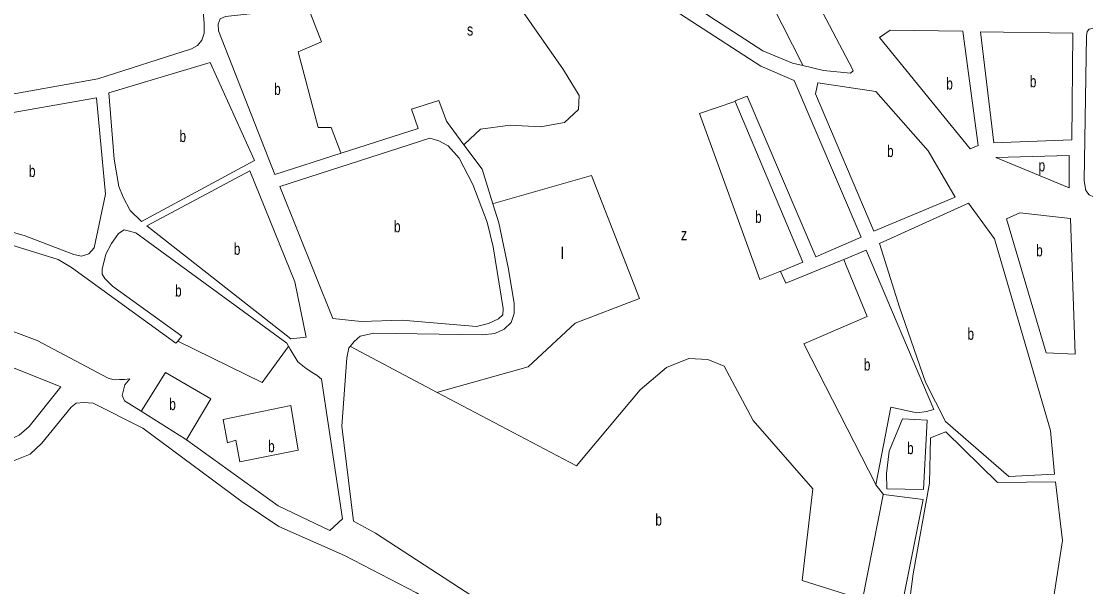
# Model space of a CAD drawing. Extents: x 639657 to 671642, y 222838 to 252123.
# Drawn here: x 648393 to 649296, y 242810 to 243290 of the extents above; entities that cross this region are included whole.
import ezdxf

# ---------------------------------------------------------------- set-up
doc = ezdxf.new("R2010")
doc.units = 0
doc.header["$LTSCALE"] = 4
doc.layers.add('1', color=7, linetype='Continuous', lineweight=13)
doc.layers.add('21', color=7, linetype='Continuous', lineweight=13)
doc.layers.add('7', color=7, linetype='Continuous')

msp = doc.modelspace()

# ---------------------------------------------------------------- linework, layer by layer
at = {"layer": '1'}
for p, q in [((648618.55, 243016.9), (648619.936, 243014.269)), ((648476.85, 242986.046), (648476.48, 242986.027)), ((648532.46, 242935.52), (648494.743, 242959.06)), ((648532.46, 242935.52), (648533.215, 242934.977))]:
    msp.add_line(p, q, dxfattribs=at)
for points in [[(649098.36, 243249.17), (648939.37, 243550.8), (648819.54, 243488)], [(648793.12, 243492.45), (648801.618, 243464.623), (648893.09, 243350.7), (648977.18, 243293.76), (649022.12, 243264.66), (649047.26, 243254.2), (649056.254, 243252.103)], [(648903.422, 243327.55), (649020.43, 243251.77), (649048.8, 243239.6), (649105.61, 243106.79), (649067.23, 243089.94), (649008.91, 243226.18), (648998.62, 243222.29), (648998.829, 243221.793)], [(648664.469, 243177.792), (648608.3, 243159.7), (648560.33, 243281.59), (648560.31, 243287.17), (648561.8, 243291.9), (648566.31, 243293.63), (648631.33, 243300.87), (648636.234, 243301.822)], [(649056.254, 243252.103), (649073.68, 243248.04), (649096.44, 243245.73), (649098.8, 243247.67), (649098.36, 243249.17)], [(648768.656, 243185.066), (648753.94, 243204.94), (648747.46, 243222.54), (648724.29, 243215.18), (648729.91, 243198.87), (648664.469, 243177.792)], [(648998.829, 243221.793), (649056.08, 243085.62), (649037.21, 243077.63)], [(648793.192, 243134.944), (648784.1, 243164.21), (648768.656, 243185.066)], [(648672.049, 243014.121), (648675.43, 243018.33), (648680.57, 243022.64), (648692.16, 243025.24), (648784.47, 243023.75), (648794.77, 243025.06), (648802.7, 243028.73), (648808.7, 243034.33), (648811.26, 243041.85), (648811.23, 243050.66), (648806.22, 243080.93), (648798.17, 243118.92), (648793.192, 243134.944)], [(648476.48, 242986.027), (648471.926, 242985.795), (648466.808, 242987.174), (648406.66, 243018.97), (648336.83, 243045), (648344.63, 243097), (648343.674, 243102.64), (648346.179, 243107.509), (648348.428, 243109.13), (648351.99, 243110.07), (648424.51, 243087.74), (648435.69, 243080.89), (648524.382, 243016.683)], [(648618.55, 243016.9), (648490.36, 243110.23), (648480.48, 243113), (648475.55, 243109.77), (648469.77, 243101.38), (648464.86, 243092.13), (648461.67, 243079.45), (648461.69, 243075.37), (648464.06, 243071.73), (648470.51, 243065.08)], [(649090.888, 243087.789), (649109.93, 243095.63), (649167.18, 242960.69), (649161.17, 242958.75), (649152.8, 242957.87), (649130.89, 242962.61), (649118.19, 242896.58), (649124.44, 242888.65)], [(649037.21, 243077.63), (649041.74, 243067.55), (649090.888, 243087.789)], [(648470.51, 243065.08), (648529.38, 243022.698), (648525.894, 243018.503), (648524.382, 243016.683)], [(648619.936, 243014.269), (648621.321, 243011.64), (648627.841, 243000.923), (648634.827, 242995.332), (648641.37, 242990.97)], [(648665.1, 242946.58), (648669.23, 243004.34), (648670.94, 243012.74), (648672.049, 243014.121)], [(648665.74, 242867.98), (648647.83, 242986.27), (648644.17, 242989.48), (648641.37, 242990.97)], [(648494.743, 242959.06), (648480.672, 242967.842), (648478.809, 242972.501), (648481.138, 242981.354), (648485.329, 242986.479), (648480.672, 242986.013), (648476.85, 242986.046)], [(648382.38, 242915.24), (648400.83, 242922.59), (648410.68, 242932.06), (648435.5, 242962.62), (648439.79, 242965.85), (648446.22, 242966.51), (648454.17, 242965.88), (648496.31, 242944.72), (648580.41, 242882.22), (648611.6, 242861.47), (648667.27, 242836.69), (648728.54, 242805.27), (648806.18, 242754.36), (648776.24, 242711.12), (648765.11, 242696.28), (648758.26, 242690.25), (648745.61, 242683.78), (648738.74, 242682.69), (648711.9, 242685.84), (648588.37, 242714.31), (648475.98, 242756.77), (648376.31, 242775.21)], [(649022.21, 242746.46), (648995.12, 242682.84), (648908.11, 242705.81), (648793.03, 242790.99), (648693.68, 242855.59), (648674.98, 242865.86), (648665.1, 242946.58)], [(648533.215, 242934.977), (648610.97, 242879.02), (648655.03, 242857.86), (648665.74, 242867.98)], [(649110.161, 242656.114), (649119.885, 242655.479), (649134.564, 242705.482), (649144.699, 242702.684), (649130.67, 242653.91), (649180.69, 242649.81), (649206.18, 242670.48), (649246.99, 242659.85), (649276.53, 242849.52), (649270.39, 242899.32), (649221.23, 242898.55), (649177.53, 242941.61), (649164.45, 242936.64), (649163.7, 242897.98), (649149.592, 242821.221), (649145.95, 242793.15), (649137.69, 242749.539)], [(649124.44, 242888.65), (649158.15, 242884.22), (649136.34, 242775.52), (649122.51, 242729.53), (649115.47, 242710.62), (649031.261, 242742.982)]]:
    msp.add_lwpolyline(points, dxfattribs=at)
for points in [[(648541.65, 243363.17), (648413.08, 243359.64), (648361.44, 243236.22), (648361.03, 243231.06), (648363.83, 243226.34), (648369.42, 243225.07), (648458.03, 243240.96), (648537.61, 243266.28), (648542.76, 243269.09), (648546.39, 243273.61), (648548.31, 243279.63), (648548.29, 243288)], [(649204.79, 243184.35), (649191.87, 243281.19), (649130.26, 243282.11), (649121.05, 243276.07), (649198.15, 243181.54)], [(649284.42, 243189.27), (649285.26, 243279.7), (649206.9, 243280.79), (649218.1, 243186.75)], [(649416.76, 243150.08), (649420.5, 243278.96), (649419.63, 243281.32), (649415.12, 243283.67), (649303.28, 243284.25), (649298.99, 243282.95), (649297.27, 243281.02), (649296.64, 243277.36), (649294.82, 243154.51), (649296.13, 243146.13), (649298.93, 243142.71), (649302.58, 243141), (649332, 243137.42), (649352.4, 243133.6), (649377.75, 243126.79), (649393.21, 243124.9), (649402.44, 243125.78), (649409.3, 243128.16), (649413.59, 243131.61), (649417.22, 243137.63), (649418.07, 243142.14)], [(648591.09, 243171.69), (648553.31, 243254.72), (648467.3, 243228.95), (648471.95, 243172.91), (648475.87, 243149.72), (648479.55, 243140.71), (648485.59, 243129.34), (648495.27, 243119.91)], [(649117.95, 243230.1), (649068.77, 243237.5), (649066.86, 243228.26), (649116.33, 243111.76), (649185.38, 243140.71), (649162.52, 243179.74)], [(648464.73, 243143.03), (648456.986, 243224.773), (648369.833, 243209.6), (648360.096, 243209.938), (648353.72, 243208.468), (648345.072, 243203.874), (648340.285, 243199.413), (648335.092, 243191.11), (648333.177, 243184.853), (648332.605, 243178.335), (648340.03, 243132.64), (648341.237, 243127.725), (648342.994, 243124.787), (648345.572, 243122.536), (648349.293, 243121.063), (648395.7, 243108.07), (648437.853, 243092.054), (648444.279, 243090.654), (648450.583, 243092.658), (648455.04, 243097.547)], [(648739.6, 243190.73), (648612.62, 243149.62), (648657.35, 243037.83), (648681.4, 243035.1), (648716.39, 243036.26), (648779.3, 243030.82), (648789.6, 243033.43), (648797.96, 243037.31), (648801.6, 243040.97), (648802.01, 243046.13), (648793.5, 243098.51), (648788.3, 243119.33), (648776.19, 243151.3), (648764.54, 243173.61), (648755.28, 243184.11), (648747.33, 243188.39)], [(649219.797, 243174.283), (649282.052, 243175.784), (649282.052, 243148.51)], [(648621.76, 243020.56), (648634.85, 243021.88), (648625.28, 243068.68), (648587.04, 243162.87), (648499.58, 243116.27)], [(649218.74, 243105.14), (649196.55, 243135.58), (649121.08, 243101.24), (649138.18, 243047.38), (649160.25, 242983.87), (649177.08, 242950.41), (649230.87, 242903.73), (649269.51, 242905.76), (649266.19, 242942.9)], [(649287.27, 243007.38), (649283.31, 243122.48), (649240.15, 243127.31), (649229, 243122.13), (649262.58, 243008.61)], [(648399.77, 242946.15), (648426.73, 242979.72), (648375.15, 243000.42), (648332.399, 243014.709), (648329.742, 243015.368), (648326.131, 243014.92), (648321.816, 243011.66), (648320.242, 243006.487), (648320.72, 243003.791), (648322.566, 243000.707), (648332.976, 242959.498), (648338.939, 242948.566), (648344.684, 242942.536), (648351.557, 242937.831), (648363.315, 242933.693), (648375.776, 242933.391), (648383.871, 242935.351), (648391.382, 242938.951)], [(649158.56, 242892.81), (649161.62, 242951.45), (649140.8, 242952.68), (649129.28, 242925.38), (649126.97, 242906.27), (649127.43, 242893.38)]]:
    msp.add_lwpolyline(points, close=True, dxfattribs=at)
at = {"layer": '21'}
for points in [[(648819.54, 243488), (648838.539, 243454.818), (648923.817, 243500.974), (648956.669, 243441.531), (648927.312, 243425.446), (648948.281, 243389.78), (648977.639, 243407.263), (649056.001, 243252.603), (649056.254, 243252.103)], [(648768.656, 243185.066), (648769.156, 243185.535), (648782.619, 243198.163), (648807.783, 243201.659), (648833.646, 243200.261), (648853.917, 243203.757), (648865.8, 243214.947), (648866.499, 243226.835), (648853.218, 243248.515), (648811.863, 243307.564)], [(648636.234, 243301.822), (648636.428, 243301.322), (648647.712, 243272.292), (648628.14, 243263.9), (648644.916, 243199.561), (648656.1, 243199.561), (648664.277, 243178.292), (648664.469, 243177.792)], [(649037.21, 243077.63), (649036.71, 243077.439), (649019.58, 243070.884), (648968.553, 243211.45), (648998.329, 243221.622), (648998.829, 243221.793)], [(648746, 242975.11), (648746.499, 242975.25), (648823.161, 242996.755), (648863.004, 243033.82), (648917.526, 243054.8), (648876.984, 243159), (648793.692, 243135.088), (648793.192, 243134.944)], [(649090.888, 243087.789), (649092.946, 243082.789), (649110.798, 243039.414), (649056.975, 243016.336), (649117.934, 242897.08), (649118.19, 242896.58)], [(648525.894, 243018.503), (648526.394, 243018.258), (648597.39, 242983.468), (648619.453, 243013.61), (648619.936, 243014.269)], [(648746, 242975.11), (648672.549, 243013.857), (648672.049, 243014.121)], [(649124.44, 242888.65), (649124.34, 242888.15), (649106.604, 242799.543), (649055.577, 242815.628), (649064.664, 242893.253), (649013.988, 242951.298), (648989.523, 242997.454), (648975.543, 243003.049), (648959.466, 243003.748), (648940.593, 242996.056), (648918.225, 242977.174), (648864.051, 242912.835), (648746, 242975.11)], [(648494.743, 242959.06), (648495.061, 242959.56), (648515.606, 242991.86), (648554.051, 242969.481), (648533.548, 242935.529), (648533.215, 242934.977)]]:
    msp.add_lwpolyline(points, dxfattribs=at)
msp.add_lwpolyline([(648564.518, 242952.1), (648621.855, 242963.887), (648628.146, 242926.123), (648578.517, 242916.332), (648575.021, 242934.515), (648568.031, 242932.417)], close=True, dxfattribs=at)

# ---------------------------------------------------------------- texts
at = {"layer": '7'}
for s, width, p in [('s', 0.8, (648771.219, 243277.605)), ('b', 0.75, (649177.796, 243231.825)), ('b', 0.75, (649248.667, 243233.77)), ('b', 0.75, (648607.653, 243227.253)), ('b', 0.75, (648527.368, 243187.315)), ('b', 0.75, (649127.573, 243174.63)), ('b', 0.75, (648399.647, 243157.713)), ('p', 0.75, (649256.085, 243162.427)), ('b', 0.75, (649015.607, 243118.802)), ('b', 0.75, (648709.3, 243110.775)), ('z', 0.8, (648952.697, 243104.115)), ('b', 0.75, (648573.427, 243091.715)), ('b', 0.75, (649254.022, 243090.422)), ('b', 0.75, (648523.586, 243056.288)), ('b', 0.75, (649195.778, 243019.655)), ('b', 0.75, (649107.874, 242993.621)), ('b', 0.75, (648518.662, 242960.081)), ('b', 0.75, (648602.543, 242924.415)), ('b', 0.75, (649144.542, 242922.745)), ('b', 0.75, (648931.028, 242862.147))]:
    msp.add_text(s, height=10, dxfattribs=dict(at, width=width)).set_placement(p)
msp.add_text('l', height=10, dxfattribs=at).set_placement((648850.643, 243088.031))

doc.saveas('drawing.dxf')
